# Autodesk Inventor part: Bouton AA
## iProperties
Created: 2010-07
Part Number: Bouton AA
Document SubType Name: Modeling
Designer: eric
Density: 1 g/cm^3
Mass: 0.000268465 g
Surface Area: 0.0704174 cm^2
Volume: 0.000268465 cm^3
Author: eric
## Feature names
1. Extrusion1
2. Chamfer1
